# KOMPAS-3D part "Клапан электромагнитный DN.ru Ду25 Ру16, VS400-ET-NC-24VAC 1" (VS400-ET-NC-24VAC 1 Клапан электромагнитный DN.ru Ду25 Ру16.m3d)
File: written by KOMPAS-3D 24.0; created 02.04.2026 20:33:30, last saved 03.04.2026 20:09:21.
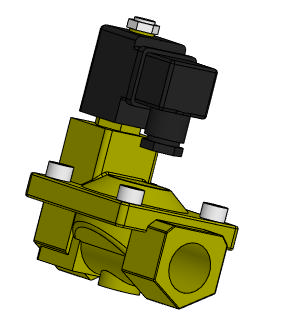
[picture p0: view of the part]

Document properties: Автор: artio; Полное имя файла: C:\Users\artio\OneDrive\Рабочий стол\Клапан электромагнитный DN.ru\VS400-ET-NC\VS400-ET-NC-24VAC 1 Клапан электромагнитный DN.ru Ду25 Ру16.m3d

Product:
- Body: Тело 1  | qty 1
    Масса: 1.76797
- Part/product: Клапан электромагнитный DN.ru Ду25 Ру16  | designation VS400-ET-NC-24VAC 1
    Масса: 1.524
    Раздел спецификации: Прочие изделия
    Примечание: D130-05489
    additional columns: ef56311e-7521-43dc-8291-0e6108b3d81d; VS400-ET-NC-220VAC 1; artio; c; Шероховатость не задана; Да

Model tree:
1. Операция без истории:1

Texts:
  VS400-ET-NC-24VAC 1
